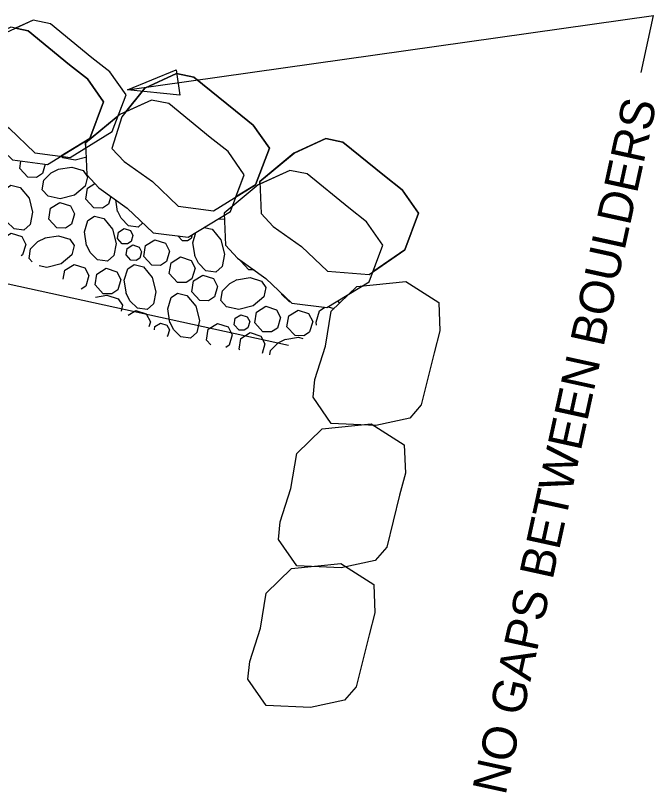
# Model space of a CAD drawing. Extents: x 2126110 to 2128246, y 1804858 to 1811658.
# Drawn here: x 2126861.3 to 2127236.7, y 1808621.8 to 1809077.2 of the extents above; entities that cross this region are included whole.
import ezdxf

# ---------------------------------------------------------------- set-up
doc = ezdxf.new("R2010")
doc.units = 0
for name, color, linetype in [('1', 7, 'Continuous'), ('DET-EARTH', 7, 'Continuous'), ('Old_Level_1', 7, 'Continuous'), ('Old_Level_41', 7, 'Continuous')]:
    doc.layers.add(name, color=color, linetype=linetype)

msp = doc.modelspace()

# ---------------------------------------------------------------- linework, layer by layer
at = {"layer": '1'}
for p in [(2126926.93, 1809033.71), (2127228.26, 1809043.85)]:
    msp.add_line(p, (2127235.55, 1809077.23), dxfattribs=at)
msp.add_lwpolyline([(2126957.68, 1809030.47), (2126926.93, 1809033.71), (2126955.59, 1809045.32)], close=True, dxfattribs=at)
at = {"layer": 'DET-EARTH'}
msp.add_line((2127021.5, 1808883.82), (2126177.68, 1809068.21), dxfattribs=at)
for points in [[(2126840.86, 1809022.91), (2126857.54, 1809011.13), (2126872.67, 1808996.67), (2126893.32, 1808994.08), (2126918.07, 1809009.17), (2126926.12, 1809030.66), (2126916.6, 1809044.3), (2126906.15, 1809052.51), (2126881.79, 1809072.32), (2126871.65, 1809074.43), (2126853.07, 1809065.96), (2126853.07, 1809065.96), (2126831.63, 1809046.57), (2126833.73, 1809030.56), (2126840.86, 1809022.91)], [(2126827.7, 1809018.8), (2126844.38, 1809007.03), (2126859.51, 1808992.57), (2126880.16, 1808989.98), (2126904.92, 1809005.07), (2126912.96, 1809026.56), (2126903.45, 1809040.2), (2126892.99, 1809048.41), (2126868.64, 1809068.21), (2126858.49, 1809070.32), (2126839.92, 1809061.86), (2126839.92, 1809061.86), (2126819.85, 1809045.23), (2126820.57, 1809026.45), (2126827.7, 1809018.8)], [(2126924.97, 1808991.67), (2126941.65, 1808979.89), (2126956.77, 1808965.43), (2126977.42, 1808962.84), (2127002.18, 1808977.93), (2127010.23, 1808999.42), (2127000.71, 1809013.06), (2126990.26, 1809021.28), (2126965.9, 1809041.08), (2126955.76, 1809043.19), (2126937.18, 1809034.73), (2126937.18, 1809034.73), (2126923.58, 1809017.91), (2126917.84, 1808999.32), (2126924.97, 1808991.67)], [(2126910.23, 1808976.17), (2126926.9, 1808964.39), (2126942.04, 1808949.93), (2126962.68, 1808947.35), (2126987.44, 1808962.43), (2126995.48, 1808983.93), (2126985.97, 1808997.57), (2126975.51, 1809005.78), (2126951.16, 1809025.58), (2126941.02, 1809027.69), (2126922.44, 1809019.23), (2126922.44, 1809019.23), (2126902.38, 1809002.6), (2126903.09, 1808983.82), (2126910.23, 1808976.17)], [(2127012.46, 1808953.58), (2127029.13, 1808941.8), (2127044.26, 1808927.35), (2127068.69, 1808925.42), (2127089.66, 1808939.84), (2127097.71, 1808961.33), (2127088.19, 1808974.97), (2127077.74, 1808983.19), (2127053.38, 1809002.99), (2127043.25, 1809005.1), (2127024.66, 1808996.64), (2127024.66, 1808996.64), (2127004.61, 1808980.01), (2127005.32, 1808961.23), (2127012.46, 1808953.58)], [(2126991.53, 1808934.94), (2127008.2, 1808923.16), (2127023.34, 1808908.7), (2127043.98, 1808906.12), (2127068.74, 1808921.2), (2127076.78, 1808942.69), (2127067.27, 1808956.33), (2127056.82, 1808964.55), (2127032.46, 1808984.35), (2127022.32, 1808986.46), (2127003.74, 1808977.99), (2127003.74, 1808977.99), (2126983.68, 1808961.37), (2126984.39, 1808942.59), (2126991.53, 1808934.94)]]:
    msp.add_lwpolyline(points, dxfattribs=at)
at = {"layer": 'Old_Level_1'}
for p, q in [((2126921.21, 1808962.4), (2126920.09, 1808969.2)), ((2126981.06, 1808957.82), (2126980.61, 1808958.31)), ((2126983.86, 1808957.76), (2126981.06, 1808957.83)), ((2126959.19, 1808945.19), (2126956.5, 1808948.12)), ((2127001.26, 1808928.07), (2126998.15, 1808928.14)), ((2127044.54, 1808906.42), (2127048.16, 1808905.56)), ((2127051.44, 1808908.82), (2127050.61, 1808909.72))]:
    msp.add_line(p, q, dxfattribs=at)
for points in [[(2126902.42, 1808993.98), (2126896.24, 1808992.42), (2126889.1, 1808993.85), (2126888.62, 1808994.38)], [(2126868.52, 1808982.42), (2126863.78, 1808987.58), (2126864.48, 1808991.95)], [(2126878.72, 1808990.16), (2126877.08, 1808984.61), (2126873.61, 1808982.3), (2126868.52, 1808982.42)], [(2126886.29, 1808987.13), (2126894.3, 1808988.44), (2126900.94, 1808986.37), (2126903.49, 1808982.61), (2126902.19, 1808977.14), (2126895.94, 1808971.96), (2126887.56, 1808969.84), (2126880.42, 1808971.26), (2126877.04, 1808974.99), (2126877.9, 1808980.74), (2126882.25, 1808985.09), (2126886.62, 1808987.25)], [(2126854.06, 1808960.61), (2126852.75, 1808968.62), (2126854.82, 1808975.26), (2126858.58, 1808977.81), (2126864.05, 1808976.51), (2126869.23, 1808970.26), (2126871.35, 1808961.88), (2126869.93, 1808954.74), (2126866.21, 1808951.36), (2126860.45, 1808952.22), (2126856.1, 1808956.58), (2126853.94, 1808960.95)], [(2126907.33, 1808964.51), (2126902.59, 1808969.67), (2126903.6, 1808976.04), (2126907.89, 1808978.68)], [(2126917.23, 1808971.23), (2126915.89, 1808966.7), (2126912.41, 1808964.39), (2126907.33, 1808964.51)], [(2126885.61, 1808952.73), (2126880.87, 1808957.89), (2126881.88, 1808964.26), (2126887.37, 1808967.65), (2126893.59, 1808965.63), (2126895.97, 1808961.03), (2126894.17, 1808954.92), (2126890.69, 1808952.62), (2126885.61, 1808952.73)], [(2126936.07, 1808955.63), (2126933.35, 1808953.16), (2126927.6, 1808954.02), (2126923.24, 1808958.37), (2126921.08, 1808962.74)], [(2126903.04, 1808942.41), (2126901.73, 1808950.42), (2126903.8, 1808957.07), (2126907.56, 1808959.62), (2126913.03, 1808958.31), (2126918.21, 1808952.06), (2126920.33, 1808943.69), (2126918.9, 1808936.55), (2126915.18, 1808933.16), (2126909.43, 1808934.02), (2126905.07, 1808938.38), (2126902.92, 1808942.75)], [(2126923.95, 1808943.4), (2126921.1, 1808946.5), (2126921.71, 1808950.32), (2126925.01, 1808952.35), (2126928.74, 1808951.14), (2126930.17, 1808948.38), (2126929.08, 1808944.71), (2126927, 1808943.33), (2126923.95, 1808943.4)], [(2126971.96, 1808953.02), (2126976.59, 1808951.92), (2126981.77, 1808945.67), (2126983.89, 1808937.29), (2126982.47, 1808930.15), (2126978.74, 1808926.77), (2126972.99, 1808927.63), (2126968.64, 1808931.98), (2126966.48, 1808936.36)], [(2126852.69, 1808942.94), (2126853.22, 1808946.24), (2126858.71, 1808949.63), (2126864.92, 1808947.61), (2126867.31, 1808943.01), (2126865.5, 1808936.9), (2126864.63, 1808936.32)], [(2126870.98, 1808932.81), (2126869.24, 1808934.73), (2126870.1, 1808940.48), (2126874.46, 1808944.84), (2126878.83, 1808946.99)], [(2126878.49, 1808946.87), (2126886.5, 1808948.18), (2126893.14, 1808946.11), (2126895.69, 1808942.35), (2126894.39, 1808936.88), (2126888.14, 1808931.7), (2126879.77, 1808929.58), (2126875.15, 1808930.5)], [(2126965, 1808948.76), (2126964.33, 1808946.5), (2126962.24, 1808945.12), (2126959.2, 1808945.19)], [(2126966.6, 1808936.02), (2126965.29, 1808944.02), (2126967.18, 1808950.1)], [(2126929.01, 1808933.78), (2126926.16, 1808936.88), (2126926.78, 1808940.7), (2126930.07, 1808942.73), (2126933.8, 1808941.52), (2126935.23, 1808938.76), (2126934.14, 1808935.09), (2126932.06, 1808933.71), (2126929.01, 1808933.78)], [(2126941.27, 1808930.82), (2126936.53, 1808935.99), (2126937.54, 1808942.36), (2126943.03, 1808945.74), (2126949.25, 1808943.72), (2126951.64, 1808939.13), (2126949.83, 1808933.01), (2126946.35, 1808930.71), (2126941.28, 1808930.83)], [(2126956.28, 1808920.77), (2126951.53, 1808925.94), (2126952.54, 1808932.31), (2126958.04, 1808935.69), (2126964.25, 1808933.67), (2126966.64, 1808929.08), (2126964.83, 1808922.96), (2126961.36, 1808920.66), (2126956.28, 1808920.77)], [(2126998.15, 1808928.14), (2126993.4, 1808933.3), (2126993.45, 1808933.58)], [(2126889.34, 1808922.64), (2126890.19, 1808927.98), (2126895.68, 1808931.36), (2126901.9, 1808929.34), (2126904.28, 1808924.75), (2126902.47, 1808918.63), (2126899.79, 1808916.85)], [(2126912.74, 1808914.17), (2126908, 1808919.33), (2126909.02, 1808925.7), (2126914.51, 1808929.09), (2126920.72, 1808927.06), (2126923.11, 1808922.47), (2126921.3, 1808916.36), (2126917.83, 1808914.05), (2126912.74, 1808914.17)], [(2126926.38, 1808914.07), (2126925.07, 1808922.08), (2126927.13, 1808928.73), (2126930.9, 1808931.28), (2126936.37, 1808929.97), (2126941.55, 1808923.72), (2126943.67, 1808915.35), (2126942.24, 1808908.21), (2126938.52, 1808904.83), (2126932.77, 1808905.68), (2126928.41, 1808910.04), (2126926.26, 1808914.41)], [(2126969.49, 1808910.12), (2126964.74, 1808915.28), (2126965.75, 1808921.65), (2126971.25, 1808925.04), (2126977.46, 1808923.01), (2126979.85, 1808918.42), (2126978.04, 1808912.31), (2126974.57, 1808910), (2126969.49, 1808910.12)], [(2126991.02, 1808922.27), (2126999.04, 1808923.59), (2127005.68, 1808921.52), (2127008.23, 1808917.76), (2127006.93, 1808912.29), (2127000.68, 1808907.11), (2126992.3, 1808904.99), (2126985.16, 1808906.41), (2126981.78, 1808910.13), (2126982.64, 1808915.89), (2126986.99, 1808920.24), (2126991.37, 1808922.4)], [(2126908.23, 1808912.18), (2126914.83, 1808913.26), (2126921.48, 1808911.2), (2126924.03, 1808907.43), (2126923.19, 1808903.9)], [(2126951.89, 1808897.27), (2126950.58, 1808905.28), (2126952.64, 1808911.92), (2126956.41, 1808914.47), (2126961.88, 1808913.17), (2126967.06, 1808906.92), (2126969.18, 1808898.55), (2126967.75, 1808891.4), (2126964.03, 1808888.02), (2126958.28, 1808888.88), (2126953.92, 1808893.24), (2126951.77, 1808897.61)], [(2127022.69, 1808909.32), (2127021.97, 1808909.43), (2127017.61, 1808913.79), (2127017.26, 1808914.51)], [(2127006.46, 1808891.85), (2127001.71, 1808897.02), (2127002.73, 1808903.39), (2127008.22, 1808906.77), (2127014.44, 1808904.75), (2127016.82, 1808900.16), (2127015.01, 1808894.04), (2127011.54, 1808891.74), (2127006.46, 1808891.85)], [(2127037.9, 1808895.68), (2127037.61, 1808897.49), (2127039.67, 1808904.14), (2127042.81, 1808906.26)], [(2126927.32, 1808901.61), (2126931.82, 1808904.38), (2126938.03, 1808902.36), (2126940.42, 1808897.76), (2126939.55, 1808894.83)], [(2126992.47, 1808892.8), (2126989.63, 1808895.9), (2126990.23, 1808899.73), (2126993.53, 1808901.75), (2126997.26, 1808900.54), (2126998.69, 1808897.79), (2126997.6, 1808894.12), (2126995.52, 1808892.74), (2126992.47, 1808892.81)], [(2127025.28, 1808889.57), (2127020.54, 1808894.74), (2127021.55, 1808901.11), (2127027.04, 1808904.49), (2127033.26, 1808902.47), (2127035.64, 1808897.88), (2127033.85, 1808891.79)], [(2126942.8, 1808893.03), (2126943.11, 1808894.92), (2126946.4, 1808896.95), (2126950.13, 1808895.74), (2126951.56, 1808892.98), (2126950.48, 1808889.31), (2126950.04, 1808889.02)], [(2126975.86, 1808884.14), (2126973.28, 1808886.94), (2126974.3, 1808893.31), (2126979.79, 1808896.69), (2126986.01, 1808894.67), (2126988.39, 1808890.08), (2126986.58, 1808883.96), (2126984.6, 1808882.65)], [(2126992.81, 1808881.26), (2126992.51, 1808881.58), (2126993.52, 1808887.95), (2126999.01, 1808891.33), (2127005.23, 1808889.31), (2127007.62, 1808884.72), (2127005.93, 1808879.03)], [(2127019.36, 1808887.36), (2127027.37, 1808888.67), (2127029.8, 1808887.92)], [(2127033.76, 1808891.71), (2127030.36, 1808889.46), (2127025.28, 1808889.58)], [(2127010.57, 1808878.24), (2127010.98, 1808880.97), (2127015.33, 1808885.33), (2127019.7, 1808887.48)]]:
    msp.add_lwpolyline(points, dxfattribs=at)
at = {"layer": 'Old_Level_41'}
for p, q in [((2126871.66, 1809074.43), (2126861.34, 1809069.73)), ((2126881.79, 1809072.32), (2126871.66, 1809074.43)), ((2126906.15, 1809052.51), (2126881.79, 1809072.32)), ((2126861.34, 1809069.73), (2126868.64, 1809068.21)), ((2126868.64, 1809068.21), (2126892.99, 1809048.41)), ((2126916.6, 1809044.3), (2126906.15, 1809052.51)), ((2126892.99, 1809048.41), (2126903.45, 1809040.2)), ((2126926.12, 1809030.66), (2126916.6, 1809044.3)), ((2126937.18, 1809034.73), (2126955.76, 1809043.19)), ((2126955.76, 1809043.19), (2126965.9, 1809041.08)), ((2126903.45, 1809040.2), (2126912.96, 1809026.56)), ((2126965.9, 1809041.08), (2126990.26, 1809021.28)), ((2126925.93, 1809020.81), (2126937.18, 1809034.73)), ((2126921.57, 1809018.5), (2126926.12, 1809030.66)), ((2126912.96, 1809026.56), (2126904.92, 1809005.07)), ((2126941.02, 1809027.69), (2126925.93, 1809020.81)), ((2126951.16, 1809025.58), (2126941.02, 1809027.69)), ((2126975.52, 1809005.78), (2126951.16, 1809025.58)), ((2126990.26, 1809021.28), (2127000.71, 1809013.06)), ((2126902.38, 1809002.6), (2126921.57, 1809018.5)), ((2127000.71, 1809013.06), (2127010.23, 1808999.42)), ((2126904.92, 1809005.07), (2126887.99, 1808994.75)), ((2126902.49, 1808999.67), (2126902.38, 1809002.6)), ((2126985.97, 1808997.57), (2126975.52, 1809005.78)), ((2127024.67, 1808996.64), (2127043.25, 1809005.1)), ((2127043.25, 1809005.1), (2127053.38, 1809002.99)), ((2127053.38, 1809002.99), (2127077.75, 1808983.19)), ((2126893.32, 1808994.08), (2126902.49, 1808999.67)), ((2126995.48, 1808983.93), (2126985.97, 1808997.57)), ((2127010.23, 1808999.42), (2127002.18, 1808977.93)), ((2126887.99, 1808994.75), (2126893.32, 1808994.08)), ((2127004.61, 1808980.01), (2127024.67, 1808996.64)), ((2126990.6, 1808970.87), (2126995.48, 1808983.93)), ((2127022.32, 1808986.46), (2127004.67, 1808978.42)), ((2127032.46, 1808984.35), (2127022.32, 1808986.46)), ((2127056.82, 1808964.55), (2127032.46, 1808984.35)), ((2127004.67, 1808978.42), (2127004.61, 1808980.01)), ((2127077.75, 1808983.19), (2127088.19, 1808974.97)), ((2127002.18, 1808977.93), (2126990.6, 1808970.87)), ((2127088.19, 1808974.97), (2127097.71, 1808961.33)), ((2127067.27, 1808956.33), (2127056.82, 1808964.55)), ((2127097.71, 1808961.33), (2127089.67, 1808939.84)), ((2127076.78, 1808942.69), (2127067.27, 1808956.33)), ((2127070.89, 1808926.93), (2127076.78, 1808942.69)), ((2127089.67, 1808939.84), (2127070.89, 1808926.93))]:
    msp.add_line(p, q, dxfattribs=at)
for points in [[(2126827.7, 1809018.8), (2126844.38, 1809007.03), (2126859.51, 1808992.57), (2126880.16, 1808989.98), (2126904.92, 1809005.07), (2126912.96, 1809026.56), (2126903.45, 1809040.2), (2126892.99, 1809048.41), (2126868.64, 1809068.21), (2126858.49, 1809070.32), (2126839.92, 1809061.86), (2126839.92, 1809061.86), (2126819.85, 1809045.23), (2126820.57, 1809026.45), (2126827.7, 1809018.8)], [(2126910.23, 1808976.17), (2126926.9, 1808964.39), (2126942.04, 1808949.93), (2126962.68, 1808947.35), (2126987.44, 1808962.43), (2126995.48, 1808983.93), (2126985.97, 1808997.57), (2126975.51, 1809005.78), (2126951.16, 1809025.58), (2126941.02, 1809027.69), (2126922.44, 1809019.23), (2126922.44, 1809019.23), (2126902.38, 1809002.6), (2126903.09, 1808983.82), (2126910.23, 1808976.17)], [(2126991.53, 1808934.94), (2127008.2, 1808923.16), (2127023.34, 1808908.7), (2127043.98, 1808906.12), (2127068.74, 1808921.2), (2127076.78, 1808942.69), (2127067.27, 1808956.33), (2127056.81, 1808964.55), (2127032.46, 1808984.35), (2127022.32, 1808986.46), (2127003.74, 1808977.99), (2127003.74, 1808977.99), (2126983.68, 1808961.37), (2126984.39, 1808942.59), (2126991.53, 1808934.94)], [(2127036.93, 1808863.87), (2127043.17, 1808883.32), (2127046.56, 1808903.97), (2127061.5, 1808918.46), (2127090.35, 1808921.3), (2127109.7, 1808908.97), (2127110.31, 1808892.35), (2127106.9, 1808879.5), (2127099.35, 1808849.03), (2127092.52, 1808841.24), (2127072.59, 1808836.83), (2127072.59, 1808836.83), (2127046.56, 1808838.04), (2127035.83, 1808853.47), (2127036.93, 1808863.87)], [(2127016.61, 1808780.44), (2127022.84, 1808799.88), (2127026.24, 1808820.54), (2127041.17, 1808835.02), (2127070.02, 1808837.86), (2127089.38, 1808825.53), (2127089.98, 1808808.92), (2127086.57, 1808796.06), (2127079.03, 1808765.6), (2127072.2, 1808757.81), (2127052.27, 1808753.4), (2127052.27, 1808753.4), (2127026.24, 1808754.61), (2127015.51, 1808770.04), (2127016.61, 1808780.44)], [(2126998.72, 1808698.57), (2127004.95, 1808718.01), (2127008.35, 1808738.66), (2127023.28, 1808753.15), (2127052.13, 1808755.99), (2127071.49, 1808743.66), (2127072.09, 1808727.04), (2127068.68, 1808714.19), (2127061.14, 1808683.73), (2127054.31, 1808675.94), (2127034.38, 1808671.53), (2127034.38, 1808671.53), (2127008.35, 1808672.74), (2126997.62, 1808688.17), (2126998.72, 1808698.57)]]:
    msp.add_lwpolyline(points, dxfattribs=at)

# ---------------------------------------------------------------- texts
at = {"layer": 'DET-EARTH'}
msp.add_text('NO GAPS BETWEEN BOULDERS', height=20, rotation=77.6735, dxfattribs=at).set_placement((2127148.71, 1808619.65))

doc.saveas('drawing.dxf')
